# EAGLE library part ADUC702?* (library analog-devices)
Precision Analog Microcontroller 12-bit Analog I/O, ARM7TDMI® MCU ADuC7022/24 Source: http://www.analog.com/UploadedFiles/Data_Sheets/288945048AD7C7019_20_1_2_4_5_6_7_0.pdf
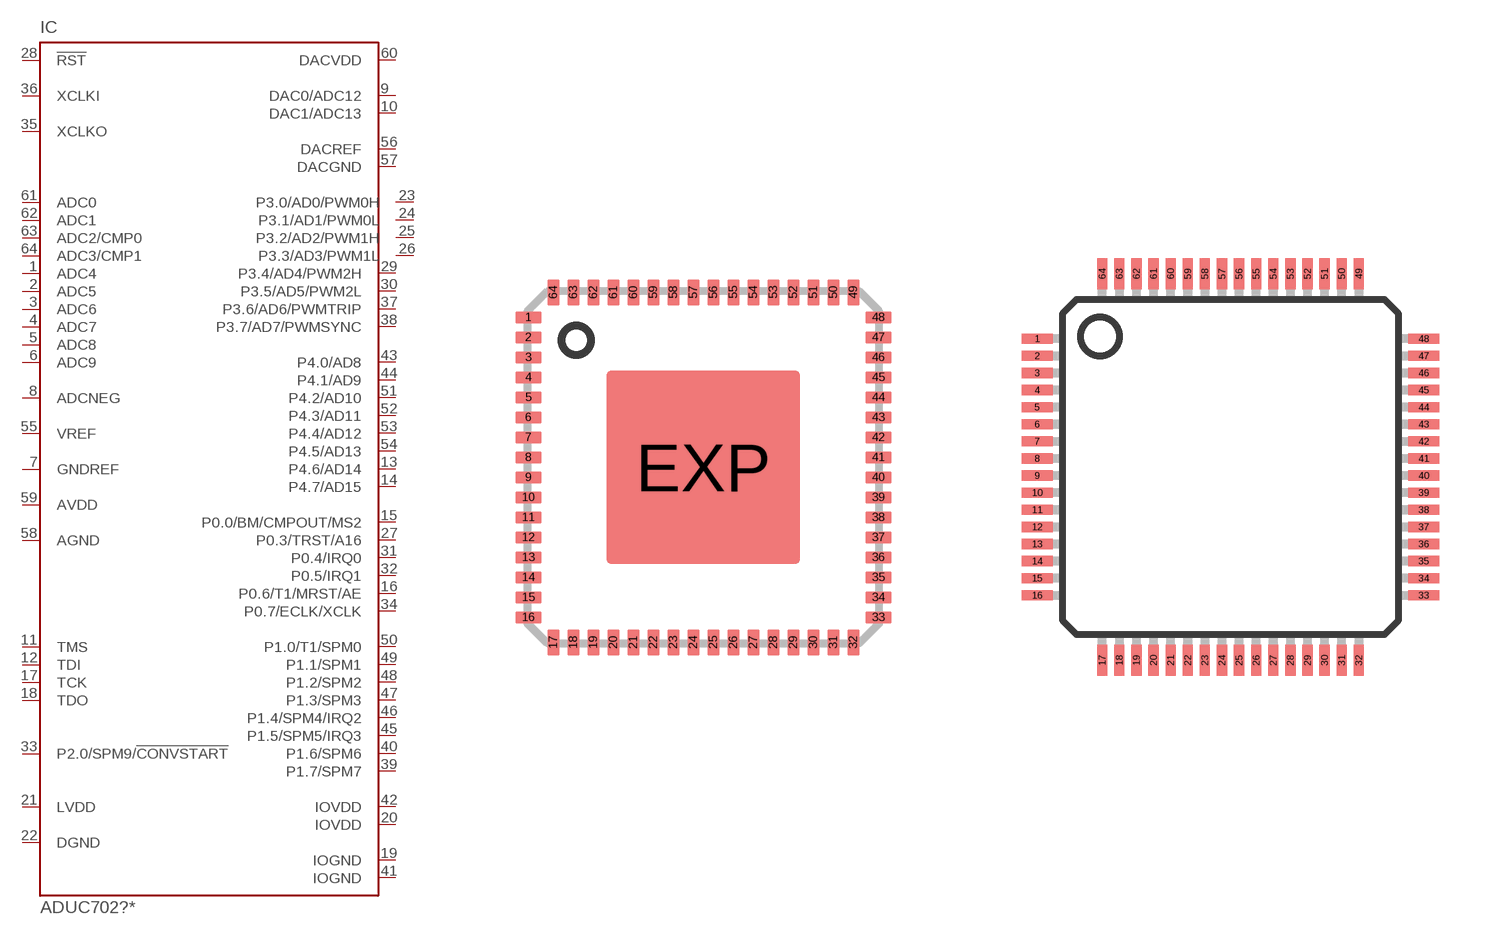
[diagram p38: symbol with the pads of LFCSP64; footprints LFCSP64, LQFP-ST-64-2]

Designator prefix IC

## ADUC7024BCPZ62 (OC_FARNELL: unknown; OC_NEWARK: unknown), ADUC7024BCPZ62-RL (OC_FARNELL: unknown; OC_NEWARK: unknown), ADUC7024BCPZ62-RL7 (OC_FARNELL: unknown; OC_NEWARK: unknown)  [LFCSP64]
1  ADC4  in
2  ADC5  in
3  ADC6  in
4  ADC7  in
5  ADC8  in
6  ADC9  in
7  GNDREF  in
8  ADCNEG  in
9  DAC0/ADC12  in
10  DAC1/ADC13  in
11  TMS  in
12  TDI  in
13  P4.6/AD14
14  P4.7/AD15
15  P0.0/BM/CMPOUT/MS2
16  P0.6/T1/MRST/AE
17  TCK  in
18  TDO  out
19  IOGND  pwr
20  IOVDD  pwr
21  LVDD  out
22  DGND  pwr
23  P3.0/AD0/PWM0H  out
24  P3.1/AD1/PWM0L  out
25  P3.2/AD2/PWM1H  out
26  P3.3/AD3/PWM1L  out
27  P0.3/TRST/A16
28  !RST  in
29  P3.4/AD4/PWM2H  out
30  P3.5/AD5/PWM2L  out
31  P0.4/IRQ0
32  P0.5/IRQ1
33  P2.0/SPM9/!CONVSTART
34  P0.7/ECLK/XCLK
35  XCLKO  out
36  XCLKI  in
37  P3.6/AD6/PWMTRIP  out
38  P3.7/AD7/PWMSYNC  out
39  P1.7/SPM7
40  P1.6/SPM6
41  IOGND  pwr
42  IOVDD  pwr
43  P4.0/AD8
44  P4.1/AD9
45  P1.5/SPM5/IRQ3
46  P1.4/SPM4/IRQ2
47  P1.3/SPM3
48  P1.2/SPM2
49  P1.1/SPM1
50  P1.0/T1/SPM0
51  P4.2/AD10
52  P4.3/AD11
53  P4.4/AD12
54  P4.5/AD13
55  VREF  pas
56  DACREF  in
57  DACGND  pwr
58  AGND  pwr
59  AVDD  pwr
60  DACVDD  pwr
61  ADC0  in
62  ADC1  in
63  ADC2/CMP0  in
64  ADC3/CMP1  in

## ADUC7024BSTZ62 (MPN: ADUC7024BSTZ62-RL; OC_FARNELL: unknown; OC_NEWARK: 12M8337), ADUC7024BSTZ62-RL (OC_FARNELL: unknown; OC_NEWARK: unknown)  [LQFP-ST-64-2]
Pads as for LFCSP64

## ADUC7025BCPZ32 (OC_FARNELL: unknown; OC_NEWARK: unknown), ADUC7025BCPZ32-RL (OC_FARNELL: unknown; OC_NEWARK: unknown), ADUC7025BCPZ32-RL7 (OC_FARNELL: unknown; OC_NEWARK: unknown), ADUC7025BCPZ62 (OC_FARNELL: unknown; OC_NEWARK: unknown), ADUC7025BCPZ62-RL (OC_FARNELL: unknown; OC_NEWARK: unknown), ADUC7025BCPZ62-RL7 (OC_FARNELL: unknown; OC_NEWARK: unknown)  [LFCSP64]
Pads as for LFCSP64

## ADUC7025BSTZ62 (MPN: ADUC7025BSTZ62-RL; OC_FARNELL: unknown; OC_NEWARK: 12M8345), ADUC7025BSTZ62-RL (OC_FARNELL: unknown; OC_NEWARK: unknown)  [LQFP-ST-64-2]
Pads as for LFCSP64

## Footprint LFCSP64 (pad centres in mm)
64-Lead Lead Frame Chip Scale Package [LFCSP] CP-64-1 9 x 9 mm Body Source: http://www.analog.com/UploadedFiles/Packages/40887351787287CP_64_1.pdf
smd 0.65 x 0.3: 1 -4.375,3.75; 2 -4.375,3.25; 3 -4.375,2.75; 4 -4.375,2.25; 5 -4.375,1.75; 6 -4.375,1.25; 7 -4.375,0.75; 8 -4.375,0.25; 9 -4.375,-0.25; 10 -4.375,-0.75; 11 -4.375,-1.25; 12 -4.375,-1.75; 13 -4.375,-2.25; 14 -4.375,-2.75; 15 -4.375,-3.25; 16 -4.375,-3.75; 33 4.375,-3.75; 34 4.375,-3.25; 35 4.375,-2.75; 36 4.375,-2.25; 37 4.375,-1.75; 38 4.375,-1.25; 39 4.375,-0.75; 40 4.375,-0.25; 41 4.375,0.25; 42 4.375,0.75; 43 4.375,1.25; 44 4.375,1.75; 45 4.375,2.25; 46 4.375,2.75; 47 4.375,3.25; 48 4.375,3.75
smd 0.3 x 0.65: 17 -3.75,-4.375; 18 -3.25,-4.375; 19 -2.75,-4.375; 20 -2.25,-4.375; 21 -1.75,-4.375; 22 -1.25,-4.375; 23 -0.75,-4.375; 24 -0.25,-4.375; 25 0.25,-4.375; 26 0.75,-4.375; 27 1.25,-4.375; 28 1.75,-4.375; 29 2.25,-4.375; 30 2.75,-4.375; 31 3.25,-4.375; 32 3.75,-4.375; 49 3.75,4.375; 50 3.25,4.375; 51 2.75,4.375; 52 2.25,4.375; 53 1.75,4.375; 54 1.25,4.375; 55 0.75,4.375; 56 0.25,4.375; 57 -0.25,4.375; 58 -0.75,4.375; 59 -1.25,4.375; 60 -1.75,4.375; 61 -2.25,4.375; 62 -2.75,4.375; 63 -3.25,4.375; 64 -3.75,4.375
smd 4.85 x 4.85: EXP 0,0

## Footprint LQFP-ST-64-2 (pad centres in mm)
64-Lead Low Profile Quad Flat Package [LQFP] (ST-64-2) COMPLIANT TO JEDEC STANDARDS MS-026-BCD Source: http://www.analog.com/UploadedFiles/Data_Sheets/288945048AD7C7019_20_1_2_4_5_6_7_0.pdf
smd 0.9 x 0.3: 1 -5.65,3.75; 2 -5.65,3.25; 3 -5.65,2.75; 4 -5.65,2.25; 5 -5.65,1.75; 6 -5.65,1.25; 7 -5.65,0.75; 8 -5.65,0.25; 9 -5.65,-0.25; 10 -5.65,-0.75; 11 -5.65,-1.25; 12 -5.65,-1.75; 13 -5.65,-2.25; 14 -5.65,-2.75; 15 -5.65,-3.25; 16 -5.65,-3.75; 33 5.65,-3.75; 34 5.65,-3.25; 35 5.65,-2.75; 36 5.65,-2.25; 37 5.65,-1.75; 38 5.65,-1.25; 39 5.65,-0.75; 40 5.65,-0.25; 41 5.65,0.25; 42 5.65,0.75; 43 5.65,1.25; 44 5.65,1.75; 45 5.65,2.25; 46 5.65,2.75; 47 5.65,3.25; 48 5.65,3.75
smd 0.3 x 0.9: 17 -3.75,-5.65; 18 -3.25,-5.65; 19 -2.75,-5.65; 20 -2.25,-5.65; 21 -1.75,-5.65; 22 -1.25,-5.65; 23 -0.75,-5.65; 24 -0.25,-5.65; 25 0.25,-5.65; 26 0.75,-5.65; 27 1.25,-5.65; 28 1.75,-5.65; 29 2.25,-5.65; 30 2.75,-5.65; 31 3.25,-5.65; 32 3.75,-5.65; 49 3.75,5.65; 50 3.25,5.65; 51 2.75,5.65; 52 2.25,5.65; 53 1.75,5.65; 54 1.25,5.65; 55 0.75,5.65; 56 0.25,5.65; 57 -0.25,5.65; 58 -0.75,5.65; 59 -1.25,5.65; 60 -1.75,5.65; 61 -2.25,5.65; 62 -2.75,5.65; 63 -3.25,5.65; 64 -3.75,5.65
